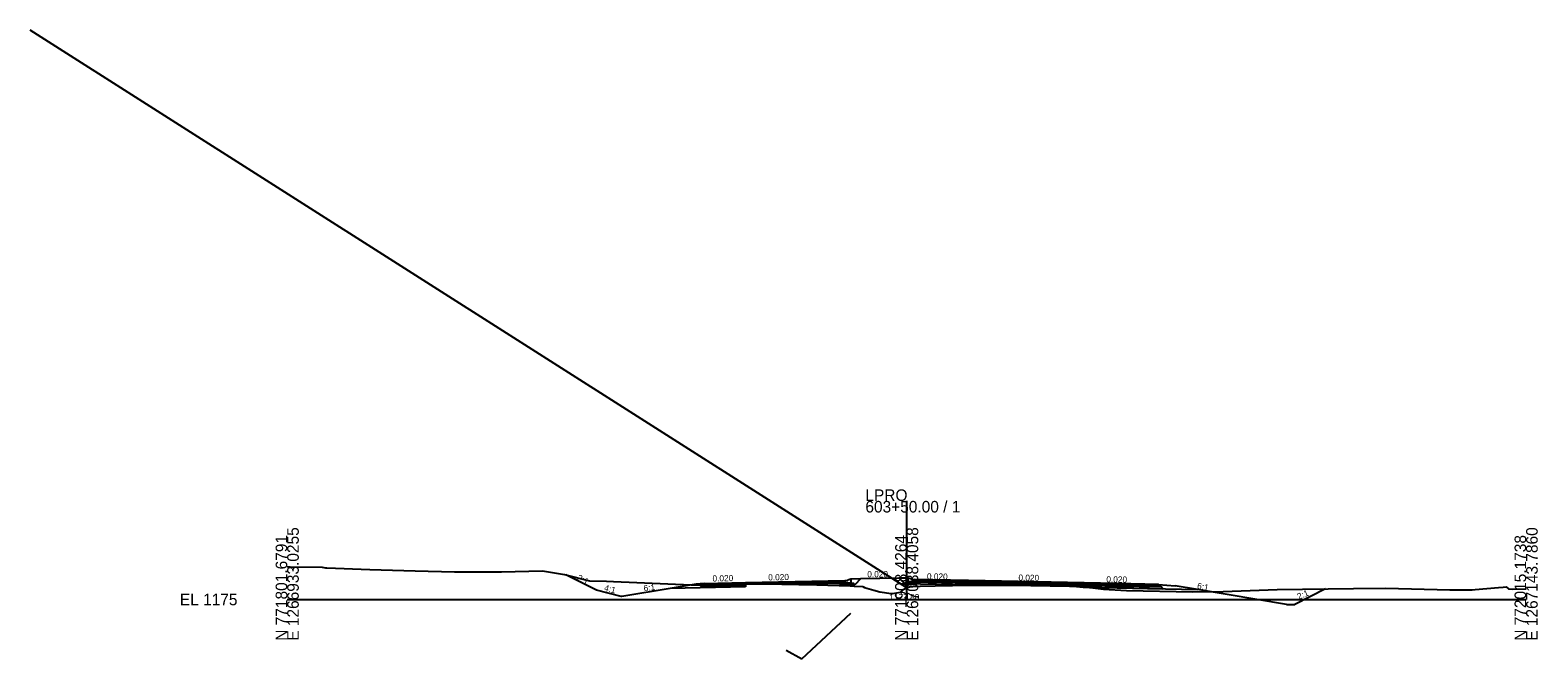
# Model space of a CAD drawing. Extents: x -3833 to 1267678, y -522 to 773248.
# Drawn here: x 937.8 to 1302.8, y 4485.6 to 4637.9 of the extents above; entities that cross this region are included whole.
import ezdxf

# ---------------------------------------------------------------- set-up
doc = ezdxf.new("R2010")
doc.units = 0
for name, color, linetype in [('Exist Cross Section Cell', 7, 'Continuous'), ('Exist XS Center Line Elevation Label', 7, 'Continuous'), ('Exist XS Ground Line', 7, 'Continuous'), ('Prop CMT DNC', 7, 'Continuous'), ('Prop CMT Pvmt Course 1', 7, 'Continuous'), ('Prop CMT Pvmt Course 2', 7, 'Continuous'), ('Prop CMT Pvmt Course 3', 7, 'Continuous'), ('Prop CMT Pvmt Course 4', 7, 'Continuous'), ('Prop CMT Shld Paved Course 1', 7, 'Continuous'), ('Prop CMT Shld Paved Course 2', 7, 'Continuous'), ('Prop CMT Shld Paved Course 4', 7, 'Continuous'), ('Prop CMT Slope Grass', 7, 'Continuous'), ('Prop CMT Subgrade Earthwork', 7, 'Continuous'), ('Prop Conc Curb and Gutter', 7, 'Continuous'), ('Prop Conc Island Cover', 7, 'Continuous'), ('Prop Corridor Mesh Bottom', 7, 'Continuous'), ('Prop XS Ditch Slope Text', 7, 'Continuous'), ('Prop XS Finish Grade', 7, 'Continuous'), ('Prop XS SE Text', 7, 'Continuous'), ('Scratch_Level_1', 7, 'Continuous'), ('Scratch_Level_5', 7, 'Continuous')]:
    doc.layers.add(name, color=color, linetype=linetype)

msp = doc.modelspace()

# ---------------------------------------------------------------- linework, layer by layer
at = {"layer": 'Exist Cross Section Cell'}
for p, q in [((1150, 4500), (1150, 4523.86)), ((1000, 4500), (1150, 4500)), ((1150, 4500), (1300, 4500))]:
    msp.add_line(p, q, dxfattribs=at)
at = {"layer": 'Exist XS Ground Line'}
for p, q in [((1000, 4507.95), (1000.68, 4507.94)), ((1000.68, 4507.94), (1008.48, 4507.8)), ((1008.48, 4507.8), (1009.23, 4507.66)), ((1009.23, 4507.66), (1009.57, 4507.66)), ((1009.57, 4507.66), (1019.99, 4507.25)), ((1019.99, 4507.25), (1031.02, 4506.96)), ((1031.02, 4506.96), (1040.53, 4506.71)), ((1040.53, 4506.71), (1044.67, 4506.68)), ((1044.67, 4506.68), (1051.88, 4506.73)), ((1051.88, 4506.73), (1061.78, 4506.94)), ((1061.78, 4506.94), (1067.11, 4506.03)), ((1067.11, 4506.03), (1073.19, 4504.51)), ((1073.19, 4504.51), (1077.32, 4504.4)), ((1077.32, 4504.4), (1079, 4504.38)), ((1079, 4504.38), (1097.81, 4503.55)), ((1097.81, 4503.55), (1102.05, 4503.43)), ((1102.05, 4503.43), (1106.13, 4503.62)), ((1106.13, 4503.62), (1107.06, 4503.67)), ((1107.06, 4503.67), (1111.55, 4503.82)), ((1111.55, 4503.82), (1115.66, 4503.76)), ((1115.66, 4503.76), (1123.9, 4503.65)), ((1123.9, 4503.65), (1128.23, 4503.51)), ((1128.23, 4503.51), (1136.35, 4503.28)), ((1136.35, 4503.28), (1137.25, 4503.23)), ((1137.25, 4503.23), (1139.37, 4503.13)), ((1139.37, 4503.13), (1139.78, 4502.86)), ((1139.78, 4502.86), (1142.03, 4502.25)), ((1142.03, 4502.25), (1143.53, 4501.83)), ((1143.53, 4501.83), (1146.26, 4501.41)), ((1146.57, 4501.46), (1148.52, 4501.78)), ((1148.52, 4501.78), (1149.31, 4502.49)), ((1149.31, 4502.49), (1150.21, 4502.89)), ((1150.21, 4502.89), (1150.92, 4503.16)), ((1150.92, 4503.16), (1151.51, 4503.18)), ((1151.51, 4503.18), (1153.27, 4503.25)), ((1153.27, 4503.25), (1156.93, 4503.31)), ((1156.93, 4503.31), (1165.31, 4503.49)), ((1165.31, 4503.49), (1171.92, 4503.47)), ((1171.92, 4503.47), (1176.21, 4503.45)), ((1176.21, 4503.45), (1180.03, 4503.38)), ((1180.03, 4503.38), (1189.43, 4503.24)), ((1189.43, 4503.24), (1191.11, 4503.13)), ((1191.11, 4503.13), (1192.77, 4503.01)), ((1192.77, 4503.01), (1193.43, 4502.95)), ((1193.43, 4502.95), (1195.06, 4502.79)), ((1195.06, 4502.79), (1197.7, 4502.51)), ((1197.7, 4502.51), (1203.2, 4502.15)), ((1203.2, 4502.15), (1219.31, 4501.86)), ((1219.31, 4501.86), (1226.64, 4501.96)), ((1226.64, 4501.96), (1239.73, 4502.4)), ((1239.73, 4502.4), (1258.18, 4502.62)), ((1258.18, 4502.62), (1265.99, 4502.77)), ((1265.99, 4502.77), (1281.54, 4502.36)), ((1281.54, 4502.36), (1281.93, 4502.34)), ((1281.93, 4502.34), (1286.9, 4502.32)), ((1286.9, 4502.32), (1287.7, 4502.43)), ((1287.7, 4502.43), (1293.35, 4502.88)), ((1293.35, 4502.88), (1294.43, 4502.98)), ((1294.43, 4502.98), (1295.13, 4503.07)), ((1295.13, 4503.07), (1295.74, 4502.59)), ((1295.74, 4502.59), (1296.68, 4502.48)), ((1296.68, 4502.48), (1300, 4502.55)), ((1146.26, 4501.41), (1146.57, 4501.46))]:
    msp.add_line(p, q, dxfattribs=at)
at = {"layer": 'Prop CMT Pvmt Course 1'}
for p, q in [((1111, 4504.08), (1135, 4504.56)), ((1135, 4504.31), (1111, 4503.83)), ((1111, 4503.83), (1111, 4504.08)), ((1111, 4504.08), (1111, 4504.08)), ((1135, 4504.56), (1135, 4504.56)), ((1135, 4504.56), (1135, 4504.56)), ((1135, 4504.56), (1135, 4504.31)), ((1135, 4504.31), (1135, 4504.31)), ((1201, 4503.84), (1165, 4504.56)), ((1165, 4504.56), (1165, 4504.56)), ((1165, 4504.56), (1165, 4504.56)), ((1165, 4504.56), (1165, 4504.31)), ((1165, 4504.31), (1195, 4503.71)), ((1165, 4504.31), (1165, 4504.31)), ((1195, 4503.96), (1195, 4503.71)), ((1201, 4503.84), (1195, 4503.96)), ((1195, 4503.71), (1195, 4503.96)), ((1195, 4503.96), (1195, 4503.96)), ((1195, 4503.96), (1195, 4503.96)), ((1195, 4503.96), (1201, 4503.84)), ((1195, 4503.71), (1201, 4503.59)), ((1201, 4503.59), (1201, 4503.84))]:
    msp.add_line(p, q, dxfattribs=at)
at = {"layer": 'Prop CMT Pvmt Course 2'}
for p, q in [((1135, 4504.31), (1135, 4504.31)), ((1135, 4504.31), (1135, 4503.98)), ((1135, 4503.98), (1135, 4503.97)), ((1150, 4504.61), (1150, 4504.61)), ((1150, 4504.61), (1150, 4504.61)), ((1150, 4504.28), (1150, 4504.28)), ((1150, 4504.28), (1150, 4504.28)), ((1165, 4504.31), (1151.91, 4504.57)), ((1151.91, 4504.24), (1165, 4503.97)), ((1165, 4503.97), (1165, 4504.31)), ((1165, 4504.31), (1165, 4504.31)), ((1165, 4503.97), (1165, 4503.97)), ((1195, 4503.71), (1195, 4503.38)), ((1201, 4503.59), (1195, 4503.71)), ((1195, 4503.38), (1201, 4503.26)), ((1201, 4503.26), (1201, 4503.59))]:
    msp.add_line(p, q, dxfattribs=at)
at = {"layer": 'Prop CMT Pvmt Course 3'}
for p, q in [((1135, 4503.98), (1137.01, 4504.02)), ((1135, 4503.98), (1135, 4503.98)), ((1137.01, 4504.02), (1137.01, 4504.02)), ((1137.01, 4504.02), (1137.01, 4504.02)), ((1137.01, 4504.02), (1137.46, 4503.57)), ((1137.3, 4503.73), (1137.3, 4503.73)), ((1149.45, 4503.83), (1149.9, 4504.28)), ((1149.9, 4504.28), (1151.91, 4504.24))]:
    msp.add_line(p, q, dxfattribs=at)
at = {"layer": 'Prop CMT Pvmt Course 4'}
for p, q in [((1134, 4503.34), (1134, 4504.54)), ((1134, 4503.5), (1137.46, 4503.57)), ((1135, 4503.98), (1135, 4503.98)), ((1135, 4503.98), (1135, 4503.97)), ((1149.45, 4503.83), (1165, 4503.52)), ((1150, 4504.28), (1150, 4504.28)), ((1150, 4504.28), (1150, 4504.28)), ((1151.91, 4504.24), (1165, 4503.97)), ((1165, 4503.97), (1165, 4503.97)), ((1165, 4503.97), (1165, 4503.97)), ((1165, 4503.97), (1165, 4503.52)), ((1195, 4503.38), (1195, 4502.92)), ((1201, 4503.26), (1195, 4503.38)), ((1195, 4502.92), (1201, 4502.8)), ((1201, 4502.8), (1201, 4503.26))]:
    msp.add_line(p, q, dxfattribs=at)
at = {"layer": 'Prop CMT Shld Paved Course 1'}
for p, q in [((1100.74, 4503.62), (1101, 4503.88)), ((1111, 4503.83), (1100.74, 4503.62)), ((1101, 4503.88), (1111, 4504.08)), ((1101, 4503.88), (1101, 4503.88)), ((1111, 4504.08), (1111, 4504.08)), ((1111, 4504.08), (1111, 4504.08)), ((1111, 4504.08), (1111, 4503.83)), ((1111, 4503.83), (1111, 4503.83)), ((1135, 4504.56), (1135, 4504.56)), ((1135, 4504.56), (1135, 4504.31)), ((1150, 4504.86), (1150, 4504.86)), ((1150, 4504.86), (1150, 4504.86)), ((1150, 4504.61), (1150, 4504.61)), ((1150, 4504.61), (1150, 4504.61)), ((1165, 4504.56), (1151.91, 4504.82)), ((1151.91, 4504.57), (1165, 4504.31)), ((1165, 4504.31), (1165, 4504.56)), ((1165, 4504.56), (1165, 4504.56)), ((1201, 4503.84), (1201, 4503.59)), ((1211, 4503.64), (1201, 4503.84)), ((1201, 4503.59), (1211.26, 4503.38)), ((1211.26, 4503.38), (1211, 4503.64))]:
    msp.add_line(p, q, dxfattribs=at)
at = {"layer": 'Prop CMT Shld Paved Course 2'}
for p, q in [((1100.4, 4503.28), (1100.74, 4503.62)), ((1111, 4503.49), (1100.4, 4503.28)), ((1100.74, 4503.62), (1111, 4503.83)), ((1100.74, 4503.62), (1100.74, 4503.62)), ((1111.55, 4503.84), (1111, 4503.83)), ((1111, 4503.83), (1111, 4503.83)), ((1111, 4503.83), (1111, 4503.83)), ((1111, 4503.83), (1111, 4503.49)), ((1111, 4503.83), (1111, 4503.83)), ((1111, 4503.83), (1111, 4503.83)), ((1111, 4503.83), (1111, 4503.8)), ((1111, 4503.8), (1111.55, 4503.82)), ((1111, 4503.8), (1111, 4503.8)), ((1111, 4503.49), (1111, 4503.49)), ((1115.66, 4503.92), (1111.55, 4503.84)), ((1111.55, 4503.84), (1111.55, 4503.84)), ((1111.55, 4503.82), (1111.55, 4503.82)), ((1111.55, 4503.82), (1115.66, 4503.76)), ((1123.9, 4504.09), (1115.66, 4503.92)), ((1115.66, 4503.92), (1115.66, 4503.92)), ((1115.66, 4503.76), (1115.66, 4503.76)), ((1115.66, 4503.76), (1120.74, 4503.69)), ((1120.74, 4503.69), (1123.9, 4503.75)), ((1128.23, 4504.17), (1123.9, 4504.09)), ((1123.9, 4504.09), (1123.9, 4504.09)), ((1123.9, 4503.75), (1128.23, 4503.84)), ((1123.9, 4503.75), (1123.9, 4503.75)), ((1123.9, 4503.75), (1123.9, 4503.75)), ((1135, 4504.31), (1128.23, 4504.17)), ((1128.23, 4504.17), (1128.23, 4504.17)), ((1128.23, 4503.84), (1135, 4503.97)), ((1128.23, 4503.84), (1128.23, 4503.84)), ((1135, 4503.97), (1135, 4504.31)), ((1135, 4504.31), (1135, 4504.31)), ((1165.31, 4504.3), (1165, 4504.31)), ((1165, 4504.31), (1165, 4504.31)), ((1165, 4504.31), (1165, 4503.97)), ((1165, 4503.97), (1165.31, 4503.97)), ((1171.92, 4504.17), (1165.31, 4504.3)), ((1165.31, 4504.3), (1165.31, 4504.3)), ((1165.31, 4503.97), (1165.31, 4503.97)), ((1165.31, 4503.97), (1171.92, 4503.84)), ((1176.21, 4504.08), (1171.92, 4504.17)), ((1171.92, 4504.17), (1171.92, 4504.17)), ((1171.92, 4503.84), (1171.92, 4503.84)), ((1171.92, 4503.84), (1176.21, 4503.75)), ((1180.03, 4504.01), (1176.21, 4504.08)), ((1176.21, 4504.08), (1176.21, 4504.08)), ((1176.21, 4504.08), (1176.21, 4504.08)), ((1176.21, 4503.75), (1176.21, 4503.75)), ((1176.21, 4503.75), (1176.21, 4503.75)), ((1176.21, 4503.75), (1180.03, 4503.67)), ((1189.43, 4503.82), (1180.03, 4504.01)), ((1180.03, 4504.01), (1180.03, 4504.01)), ((1180.03, 4504.01), (1180.03, 4504.01)), ((1180.03, 4503.67), (1180.03, 4503.67)), ((1180.03, 4503.67), (1180.03, 4503.67)), ((1180.03, 4503.67), (1189.43, 4503.49)), ((1191.11, 4503.79), (1189.43, 4503.82)), ((1189.43, 4503.82), (1189.43, 4503.82)), ((1189.43, 4503.82), (1189.43, 4503.82)), ((1189.43, 4503.49), (1189.43, 4503.49)), ((1189.43, 4503.49), (1189.43, 4503.49)), ((1189.43, 4503.49), (1191.11, 4503.45)), ((1192.77, 4503.75), (1191.11, 4503.79)), ((1191.11, 4503.79), (1191.11, 4503.79)), ((1191.11, 4503.45), (1191.11, 4503.45)), ((1191.11, 4503.45), (1192.77, 4503.42)), ((1193.43, 4503.74), (1192.77, 4503.75)), ((1192.77, 4503.42), (1193.43, 4503.41)), ((1195, 4503.71), (1193.43, 4503.74)), ((1193.43, 4503.74), (1193.43, 4503.74)), ((1193.43, 4503.41), (1193.43, 4503.41)), ((1193.43, 4503.41), (1195, 4503.37)), ((1195, 4503.37), (1195, 4503.71)), ((1195, 4503.71), (1195, 4503.71)), ((1195, 4503.71), (1195, 4503.71)), ((1195, 4503.37), (1195, 4503.37)), ((1201, 4503.59), (1201, 4503.26)), ((1211.26, 4503.38), (1201, 4503.59)), ((1201, 4503.26), (1211.59, 4503.05)), ((1211.59, 4503.05), (1211.26, 4503.38))]:
    msp.add_line(p, q, dxfattribs=at)
at = {"layer": 'Prop CMT Shld Paved Course 4'}
for p, q in [((1099.94, 4502.82), (1100.4, 4503.28)), ((1111, 4503.04), (1099.94, 4502.82)), ((1100.4, 4503.28), (1100.9, 4503.29)), ((1100.9, 4503.29), (1111, 4503.49)), ((1111, 4503.49), (1111, 4503.04)), ((1201, 4503.26), (1201, 4502.8)), ((1211.09, 4503.06), (1201, 4503.26)), ((1201, 4502.8), (1212.06, 4502.58)), ((1211.59, 4503.05), (1211.09, 4503.06)), ((1212.06, 4502.58), (1211.59, 4503.05))]:
    msp.add_line(p, q, dxfattribs=at)
at = {"layer": 'Prop CMT Slope Grass'}
for p, q in [((1148.07, 4505.21), (1150.4, 4505.25)), ((1099, 4503.72), (1092.72, 4502.67)), ((1101, 4503.88), (1099, 4503.72)), ((1136.51, 4504.99), (1138.93, 4505.04)), ((1211, 4503.64), (1215, 4503.32)), ((1220.43, 4502.41), (1215, 4503.32))]:
    msp.add_line(p, q, dxfattribs=at)
at = {"layer": 'Prop CMT Subgrade Earthwork'}
for p, q in [((1148.07, 4505.21), (1149.45, 4503.83)), ((1111, 4503.04), (1092.72, 4502.67)), ((1111, 4503.8), (1111, 4503.04)), ((1137.46, 4503.57), (1134, 4503.5)), ((1134, 4503.5), (1134, 4503.34)), ((1138.93, 4505.04), (1137.46, 4503.57)), ((1149.45, 4503.83), (1165, 4503.52)), ((1165, 4503.52), (1165, 4503.48)), ((1193.42, 4502.95), (1220.43, 4502.41))]:
    msp.add_line(p, q, dxfattribs=at)
at = {"layer": 'Prop Conc Curb and Gutter'}
for p, q in [((1150.4, 4504.27), (1150.4, 4505.25)), ((1150.4, 4505.25), (1150.4, 4505.25)), ((1150.4, 4505.25), (1150.4, 4505.25)), ((1150.4, 4505.25), (1151.15, 4505)), ((1135, 4504.56), (1135.75, 4504.57)), ((1135, 4503.98), (1135, 4504.56)), ((1135, 4504.56), (1135, 4504.56)), ((1136.51, 4504.01), (1135, 4503.98)), ((1135.75, 4504.74), (1136.51, 4504.99)), ((1135.75, 4504.57), (1135.75, 4504.74)), ((1135.75, 4504.74), (1135.75, 4504.74)), ((1135.75, 4504.57), (1135.75, 4504.57)), ((1136.51, 4504.99), (1136.51, 4504.99)), ((1136.51, 4504.99), (1136.51, 4504.99)), ((1136.51, 4504.99), (1136.51, 4504.01)), ((1136.51, 4504.01), (1136.51, 4504.01)), ((1151.91, 4504.24), (1150.4, 4504.27)), ((1150.4, 4504.27), (1150.4, 4504.27)), ((1151.15, 4505), (1151.15, 4505)), ((1151.15, 4505), (1151.16, 4504.84)), ((1151.16, 4504.84), (1151.91, 4504.82)), ((1151.16, 4504.84), (1151.16, 4504.84)), ((1151.91, 4504.82), (1151.91, 4504.82)), ((1151.91, 4504.82), (1151.91, 4504.24))]:
    msp.add_line(p, q, dxfattribs=at)
at = {"layer": 'Prop Conc Island Cover'}
for p, q in [((1136.51, 4504.99), (1136.51, 4504.74)), ((1136.51, 4504.99), (1136.51, 4504.99)), ((1136.51, 4504.74), (1136.51, 4504.74))]:
    msp.add_line(p, q, dxfattribs=at)
at = {"layer": 'Prop Corridor Mesh Bottom'}
for p, q in [((1111, 4504.08), (1111, 4503.83)), ((1135, 4504.56), (1135, 4504.31)), ((1165, 4504.56), (1165, 4504.31)), ((1201, 4503.84), (1201, 4503.59))]:
    msp.add_line(p, q, dxfattribs=at)
at = {"layer": 'Prop XS Finish Grade'}
for p, q in [((1074.9, 4502.22), (1067.43, 4505.95)), ((1138.93, 4505.04), (1148.07, 4505.21)), ((1080.9, 4500.72), (1074.9, 4502.22)), ((1092.72, 4502.67), (1081, 4500.72)), ((1136.51, 4504.99), (1136.51, 4504.99)), ((1211, 4503.64), (1215, 4503.32)), ((1215, 4503.32), (1215, 4503.32)), ((1242, 4498.82), (1220.43, 4502.41)), ((1251.44, 4502.54), (1244, 4498.82)), ((1080.95, 4500.72), (1080.9, 4500.72)), ((1081, 4500.72), (1080.95, 4500.72)), ((1242, 4498.82), (1244, 4498.82))]:
    msp.add_line(p, q, dxfattribs=at)
at = {"layer": 'Scratch_Level_1'}
msp.add_line((1150, 4502.8), (937.75, 4637.86), dxfattribs=at)
at = {"layer": 'Scratch_Level_5'}
for p, q in [((1124.62, 4485.62), (1136.47, 4496.65)), ((1120.83, 4487.73), (1124.62, 4485.62))]:
    msp.add_line(p, q, dxfattribs=at)

# ---------------------------------------------------------------- texts
at = {"layer": 'Exist Cross Section Cell'}
for s, p in [('603+50.00 / 1', (1140, 4521.06)), ('LPRO', (1140, 4523.86)), ('EL 1175', (974, 4498.6))]:
    msp.add_text(s, height=2.8, dxfattribs=at).set_placement(p)
for s, p in [('E 1266933.0255', (1002.8, 4490)), ('E 1267038.4058', (1152.8, 4490)), ('E 1267143.7860', (1302.8, 4490)), ('N 771801.6791', (1000, 4490)), ('N 771908.4264', (1150, 4490)), ('N 772015.1738', (1300, 4490))]:
    msp.add_text(s, height=2.8, rotation=90, dxfattribs=at).set_placement(p)
at = {"layer": 'Exist XS Center Line Elevation Label'}
msp.add_text('1177.80', height=1.5, dxfattribs=at).set_placement((1145.8, 4499.83))
at = {"layer": 'Prop CMT DNC'}
for p in [(1063.83, 4506.59), (1101, 4503.88), (1111, 4504.08), (1111, 4504.08), (1135, 4504.56), (1135, 4504.56), (1135.75, 4504.57), (1150, 4504.86), (1151.16, 4504.84), (1165, 4504.56), (1165, 4504.56), (1201, 4503.84), (1201, 4503.84), (1211, 4503.64), (1246.04, 4502.48), (1080.95, 4500.72), (1081, 4500.72)]:
    msp.add_text('X', height=0.00025, dxfattribs=at).set_placement(p)
at = {"layer": 'Prop XS Ditch Slope Text'}
for s, rotation, p in [('2:1', 333.2561, (1070.04, 4504.77)), ('4:1', 345.1523, (1076.63, 4502.16)), ('6:1', 6.8342, (1086.39, 4501.96)), ('6:1', 349.0214, (1220.23, 4502.63)), ('2:1', 22.8609, (1244.94, 4499.94))]:
    msp.add_text(s, height=1.5, rotation=rotation, dxfattribs=at).set_placement(p)
at = {"layer": 'Prop XS SE Text'}
for rotation, p in [(1.397, (1103, 4504.33)), (1.397, (1116.49, 4504.59)), (0.2693, (1140.47, 4505.37)), (358.8542, (1154.9, 4504.87)), (358.8542, (1177.05, 4504.55)), (358.8542, (1198.34, 4504.15))]:
    msp.add_text('0.020', height=1.5, rotation=rotation, dxfattribs=at).set_placement(p)

doc.saveas('drawing.dxf')
